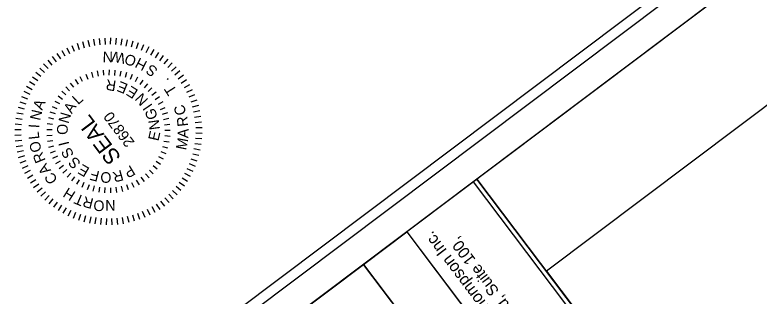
# Model space of a CAD drawing. Extents: x 1262749 to 1264921, y 774795 to 776798.
# Drawn here: x 1263030.3 to 1263352.6, y 776215.8 to 776337.8 of the extents above; entities that cross this region are included whole.
import ezdxf

# ---------------------------------------------------------------- set-up
doc = ezdxf.new("R2010")
doc.units = 0
for name, color, linetype in [('Default', 7, 'Continuous'), ('Prop Vertical Profile Curve Label', 7, 'Continuous'), ('Sheet Border Standard 30in CELL', 7, 'Continuous'), ('Sheet Data Field CELL', 7, 'Continuous'), ('Sheet Layout Plan Border', 7, 'Continuous'), ('Sheet Plan CELL', 7, 'Continuous'), ('Sheet Plan Layout CELL', 7, 'Continuous'), ('Sheet Plot Border Inside CELL', 7, 'Continuous'), ('Sheet Plot Border Outside CELL', 7, 'Continuous')]:
    doc.layers.add(name, color=color, linetype=linetype)

msp = doc.modelspace()

# ---------------------------------------------------------------- linework, layer by layer
at = {"layer": 'Default'}
for p, q in [((1263181.34, 776229.57), (1263200.1, 776243.71)), ((1263200.09, 776243.7), (1263320.41, 776083.96)), ((1263301.64, 776069.83), (1263181.33, 776229.56))]:
    msp.add_line(p, q, dxfattribs=at)
at = {"layer": 'Prop Vertical Profile Curve Label'}
for p, q in [((1263059.59, 776326.23), (1263060.36, 776323.58)), ((1263061.96, 776326.84), (1263062.57, 776324.15)), ((1263064.37, 776327.31), (1263064.81, 776324.58)), ((1263066.8, 776327.63), (1263067.07, 776324.88)), ((1263069.24, 776327.8), (1263069.35, 776325.04)), ((1263071.69, 776327.82), (1263071.63, 776325.06)), ((1263074.14, 776327.7), (1263073.91, 776324.94)), ((1263076.57, 776327.42), (1263076.18, 776324.69)), ((1263078.98, 776327.01), (1263078.43, 776324.3)), ((1263081.37, 776326.44), (1263080.65, 776323.77)), ((1263052.75, 776323.57), (1263053.99, 776321.09)), ((1263054.98, 776324.59), (1263056.06, 776322.05)), ((1263057.26, 776325.49), (1263058.19, 776322.88)), ((1263083.71, 776325.74), (1263082.84, 776323.12)), ((1263086.01, 776324.89), (1263084.98, 776322.33)), ((1263088.26, 776323.91), (1263087.07, 776321.41)), ((1263046.51, 776319.71), (1263048.17, 776317.5)), ((1263048.52, 776321.12), (1263050.04, 776318.81)), ((1263050.6, 776322.4), (1263051.98, 776320.01)), ((1263090.43, 776322.79), (1263089.1, 776320.37)), ((1263092.54, 776321.54), (1263091.06, 776319.2)), ((1263094.57, 776320.17), (1263092.95, 776317.93)), ((1263042.78, 776316.54), (1263044.69, 776314.54)), ((1263044.6, 776318.18), (1263046.39, 776316.07)), ((1263096.52, 776318.68), (1263094.76, 776316.54)), ((1263098.36, 776317.07), (1263096.49, 776315.04)), ((1263041.06, 776314.79), (1263043.09, 776312.91)), ((1263065.94, 776313.55), (1263066.36, 776311.29)), ((1263068.5, 776313.9), (1263068.71, 776311.61)), ((1263071.08, 776314.01), (1263071.06, 776311.7)), ((1263073.66, 776313.86), (1263073.42, 776311.57)), ((1263076.21, 776313.46), (1263075.75, 776311.21)), ((1263100.11, 776315.36), (1263098.12, 776313.45)), ((1263101.75, 776313.54), (1263099.64, 776311.75)), ((1263037.96, 776311), (1263040.21, 776309.38)), ((1263039.46, 776312.94), (1263041.6, 776311.19)), ((1263059.62, 776308.96), (1263058.56, 776311.01)), ((1263060.99, 776312.12), (1263061.84, 776309.98)), ((1263063.43, 776312.95), (1263064.07, 776310.74)), ((1263078.71, 776312.82), (1263078.04, 776310.62)), ((1263081.14, 776311.95), (1263080.25, 776309.82)), ((1263083.47, 776310.84), (1263082.39, 776308.81)), ((1263103.28, 776311.63), (1263101.07, 776309.97)), ((1263035.35, 776306.86), (1263037.77, 776305.52)), ((1263036.59, 776308.97), (1263038.93, 776307.49)), ((1263054.3, 776308.26), (1263055.73, 776306.45)), ((1263056.4, 776309.76), (1263057.65, 776307.82)), ((1263085.69, 776309.51), (1263084.41, 776307.59)), ((1263087.76, 776307.97), (1263086.31, 776306.19)), ((1263104.69, 776309.62), (1263102.39, 776308.1)), ((1263105.98, 776307.54), (1263103.59, 776306.16)), ((1263034.23, 776304.68), (1263036.73, 776303.49)), ((1263050.58, 776304.69), (1263052.32, 776303.19)), ((1263052.35, 776306.56), (1263053.94, 776304.9)), ((1263089.68, 776306.24), (1263088.06, 776304.61)), ((1263091.43, 776304.34), (1263089.65, 776302.87)), ((1263107.14, 776305.38), (1263104.67, 776304.15)), ((1263033.25, 776302.44), (1263035.81, 776301.41)), ((1263047.61, 776300.47), (1263049.61, 776299.33)), ((1263048.99, 776302.65), (1263050.88, 776301.32)), ((1263092.98, 776302.28), (1263091.07, 776300.98)), ((1263108.16, 776303.16), (1263105.62, 776302.07)), ((1263109.06, 776300.88), (1263106.45, 776299.95)), ((1263031.7, 776297.8), (1263034.36, 776297.08)), ((1263032.4, 776300.14), (1263035.02, 776299.26)), ((1263046.45, 776298.16), (1263048.55, 776297.23)), ((1263094.32, 776300.07), (1263092.3, 776298.97)), ((1263093.33, 776296.83), (1263095.45, 776297.73)), ((1263109.81, 776298.55), (1263107.15, 776297.78)), ((1263031.13, 776295.41), (1263033.84, 776294.86)), ((1263045.51, 776295.76), (1263047.7, 776295.03)), ((1263096.34, 776295.33), (1263094.14, 776294.63)), ((1263110.41, 776296.17), (1263107.72, 776295.57)), ((1263030.71, 776293), (1263033.45, 776292.61)), ((1263044.36, 776290.73), (1263046.64, 776290.43)), ((1263044.81, 776293.27), (1263047.05, 776292.75)), ((1263096.99, 776292.83), (1263094.74, 776292.35)), ((1263110.88, 776293.77), (1263108.15, 776293.33)), ((1263111.2, 776291.34), (1263108.45, 776291.07)), ((1263030.32, 776288.11), (1263033.08, 776288.06)), ((1263030.44, 776290.56), (1263033.2, 776290.34)), ((1263044.14, 776288.16), (1263046.45, 776288.08)), ((1263097.41, 776290.28), (1263095.12, 776290.02)), ((1263097.57, 776287.7), (1263095.27, 776287.66)), ((1263111.37, 776288.9), (1263108.61, 776288.79)), ((1263030.34, 776285.67), (1263033.1, 776285.78)), ((1263044.18, 776285.57), (1263046.49, 776285.72)), ((1263097.49, 776285.12), (1263095.19, 776285.31)), ((1263111.39, 776286.45), (1263108.63, 776286.5)), ((1263030.51, 776283.23), (1263033.26, 776283.5)), ((1263030.83, 776280.79), (1263033.56, 776281.24)), ((1263044.48, 776283.01), (1263046.75, 776283.38)), ((1263045.01, 776280.48), (1263047.24, 776281.07)), ((1263097.16, 776282.56), (1263094.89, 776282.97)), ((1263111, 776281.57), (1263108.26, 776281.96)), ((1263111.27, 776284), (1263108.51, 776284.22)), ((1263031.3, 776278.39), (1263033.99, 776279)), ((1263045.79, 776278.02), (1263047.95, 776278.82)), ((1263095.76, 776277.59), (1263093.62, 776278.43)), ((1263096.58, 776280.04), (1263094.36, 776280.67)), ((1263110.58, 776279.16), (1263107.87, 776279.71)), ((1263031.9, 776276.02), (1263034.56, 776276.78)), ((1263032.65, 776273.69), (1263035.26, 776274.62)), ((1263046.8, 776275.64), (1263048.87, 776276.65)), ((1263048.04, 776273.38), (1263050, 776274.57)), ((1263094.71, 776275.24), (1263092.65, 776276.27)), ((1263109.31, 776274.43), (1263106.69, 776275.3)), ((1263110.01, 776276.77), (1263107.35, 776277.49)), ((1263033.55, 776271.4), (1263036.09, 776272.49)), ((1263049.48, 776271.24), (1263051.32, 776272.62)), ((1263091.95, 776270.88), (1263090.14, 776272.29)), ((1263093.44, 776272.99), (1263091.49, 776274.22)), ((1263108.46, 776272.13), (1263105.9, 776273.16)), ((1263034.57, 776269.18), (1263037.04, 776270.42)), ((1263035.73, 776267.03), (1263038.12, 776268.41)), ((1263051.13, 776269.25), (1263052.83, 776270.8)), ((1263052.96, 776267.43), (1263054.51, 776269.14)), ((1263088.41, 776267.13), (1263086.9, 776268.86)), ((1263090.27, 776268.92), (1263088.6, 776270.5)), ((1263106.36, 776267.71), (1263103.94, 776269.04)), ((1263107.48, 776269.88), (1263104.98, 776271.07)), ((1263037.02, 776264.94), (1263039.32, 776266.47)), ((1263054.96, 776265.8), (1263056.33, 776267.65)), ((1263057.11, 776264.36), (1263058.3, 776266.34)), ((1263059.39, 776263.14), (1263060.38, 776265.22)), ((1263081.91, 776262.95), (1263080.96, 776265.05)), ((1263084.21, 776264.13), (1263083.05, 776266.12)), ((1263086.38, 776265.53), (1263085.04, 776267.4)), ((1263103.75, 776263.57), (1263101.5, 776265.19)), ((1263105.12, 776265.59), (1263102.78, 776267.07)), ((1263038.43, 776262.94), (1263040.64, 776264.6)), ((1263039.96, 776261.02), (1263042.07, 776262.81)), ((1263061.77, 776262.15), (1263062.56, 776264.32)), ((1263064.24, 776261.39), (1263064.81, 776263.62)), ((1263066.77, 776260.87), (1263067.12, 776263.15)), ((1263069.34, 776260.6), (1263069.47, 776262.9)), ((1263071.92, 776260.58), (1263071.83, 776262.88)), ((1263074.49, 776260.81), (1263074.18, 776263.09)), ((1263077.03, 776261.28), (1263076.5, 776263.52)), ((1263079.51, 776262), (1263078.76, 776264.18)), ((1263102.25, 776261.62), (1263100.11, 776263.37)), ((1263041.6, 776259.21), (1263043.59, 776261.12)), ((1263043.35, 776257.49), (1263045.22, 776259.52)), ((1263097.11, 776256.39), (1263095.32, 776258.49)), ((1263098.93, 776258.03), (1263097.02, 776260.02)), ((1263100.65, 776259.77), (1263098.62, 776261.65)), ((1263045.19, 776255.89), (1263046.95, 776258.02)), ((1263047.14, 776254.39), (1263048.76, 776256.64)), ((1263049.17, 776253.02), (1263050.65, 776255.36)), ((1263093.19, 776253.45), (1263091.67, 776255.75)), ((1263095.2, 776254.86), (1263093.54, 776257.07)), ((1263051.28, 776251.78), (1263052.61, 776254.19)), ((1263053.46, 776250.66), (1263054.64, 776253.16)), ((1263055.7, 776249.67), (1263056.73, 776252.24)), ((1263086.73, 776249.97), (1263085.65, 776252.51)), ((1263088.96, 776251), (1263087.72, 776253.47)), ((1263091.11, 776252.16), (1263089.73, 776254.55)), ((1263058, 776248.83), (1263058.87, 776251.45)), ((1263060.34, 776248.12), (1263061.06, 776250.79)), ((1263062.73, 776247.56), (1263063.28, 776250.27)), ((1263065.14, 776247.14), (1263065.53, 776249.88)), ((1263067.57, 776246.87), (1263067.8, 776249.62)), ((1263070.02, 776246.74), (1263070.08, 776249.51)), ((1263072.47, 776246.77), (1263072.36, 776249.53)), ((1263074.91, 776246.94), (1263074.64, 776249.69)), ((1263077.34, 776247.26), (1263076.9, 776249.99)), ((1263079.75, 776247.73), (1263079.14, 776250.42)), ((1263082.12, 776248.33), (1263081.35, 776250.99)), ((1263084.45, 776249.08), (1263083.52, 776251.69))]:
    msp.add_line(p, q, dxfattribs=at)
at = {"layer": 'Sheet Border Standard 30in CELL'}
msp.add_lwpolyline([(1263151.63, 776082.06), (1263091.48, 776161.91), (1263181.32, 776229.57), (1263241.46, 776149.72)], close=True, dxfattribs=at)
at = {"layer": 'Sheet Data Field CELL'}
msp.add_lwpolyline([(1263349.24, 776105.68), (1263228.9, 776265.45), (1263200.06, 776243.74), (1263320.41, 776083.96)], close=True, dxfattribs=at)
at = {"layer": 'Sheet Layout Plan Border'}
msp.add_lwpolyline([(1264772.58, 775612.83), (1263930.27, 776731.11), (1263260.5, 776226.63), (1263374.36, 776075.45), (1263205.44, 775948.22), (1263933.87, 774981.11)], close=True, dxfattribs=at)
at = {"layer": 'Sheet Plan CELL'}
msp.add_lwpolyline([(1263061.47, 776139.35), (1263963.95, 774941.17), (1264802.66, 775572.89), (1263900.19, 776771.05)], close=True, dxfattribs=at)
at = {"layer": 'Sheet Plan Layout CELL'}
for points in [[(1263963.99, 774941.16), (1264802.66, 775572.89), (1263900.2, 776771.04), (1263230.42, 776266.56), (1263374.36, 776075.45), (1263205.44, 775948.22)], [(1263374.36, 776075.45), (1263230.41, 776266.58), (1263061.46, 776139.36), (1263205.44, 775948.22)]]:
    msp.add_lwpolyline(points, close=True, dxfattribs=at)
at = {"layer": 'Sheet Plot Border Inside CELL'}
msp.add_lwpolyline([(1264897.01, 775451.8), (1263894.68, 776782.53), (1263051.98, 776147.82), (1264054.31, 774817.07)], close=True, dxfattribs=at)
at = {"layer": 'Sheet Plot Border Outside CELL'}
msp.add_lwpolyline([(1264920.81, 775453.45), (1263907.95, 776798.18), (1263033.3, 776139.38), (1264046.16, 774794.65)], close=True, dxfattribs=at)

# ---------------------------------------------------------------- texts
at = {"layer": 'Prop Vertical Profile Curve Label'}
for s, height, rotation, p in [('N', 4.6, 179.1043, (1263072.81, 776321.85)), ('W', 4.6, 170.2216, (1263078.41, 776321.08)), ('O', 4.6, 161.339, (1263083.33, 776319.58)), ('H', 4.6, 152.5164, (1263087.98, 776317.37)), ('S', 4.6, 143.5138, (1263092.56, 776314.25)), ('.', 4.6, 130.7295, (1263097.31, 776309.58)), ('R', 4.6, 171.4621, (1263074.43, 776309.24)), ('E', 4.6, 157.691, (1263079.62, 776307.66)), ('E', 4.6, 147.7051, (1263084.03, 776305.06)), ('N', 4.6, 132.3131, (1263088.35, 776301.02)), ('T', 4.6, 122.9872, (1263100.68, 776304.87)), ('L', 4.6, 42.7678, (1263057.72, 776298.63)), ('A', 4.6, 67.4143, (1263042.11, 776296.24)), ('A', 4.6, 58.0641, (1263054.97, 776294.71)), ('I', 4.6, 124.6834, (1263090.1, 776298.43)), ('C', 4.6, 105.1918, (1263104.61, 776294.98)), ('N', 4.6, 77.1818, (1263041.22, 776291.77)), ('N', 4.6, 73.3603, (1263053.47, 776290.43)), ('SEAL', 6.909, 126.8972, (1263076.63, 776276.14)), ('26870', 4.602, 126.8972, (1263082.33, 776282.64)), ('G', 4.6, 106.5886, (1263092.22, 776293.16)), ('N', 4.6, 97.8224, (1263093.2, 776288.26)), ('R', 4.6, 96.2194, (1263105.4, 776289.62)), ('I', 4.6, 86.4763, (1263040.87, 776288.62)), ('O', 4.6, 88.6566, (1263053.14, 776285.74)), ('E', 4.6, 76.9673, (1263092.45, 776282.87)), ('A', 4.6, 87.5468, (1263105.36, 776284.31)), ('L', 4.6, 96.0518, (1263040.96, 776284.05)), ('M', 4.6, 78.904, (1263104.48, 776278.95)), ('O', 4.6, 109.188, (1263042.13, 776279.08)), ('I', 4.6, 103.9528, (1263053.93, 776281.69)), ('R', 4.6, 112.2449, (1263043.75, 776274.71)), ('S', 4.6, 119.2491, (1263056.07, 776277.18)), ('S', 4.6, 134.5453, (1263059.14, 776273.74)), ('A', 4.6, 124.2542, (1263046.13, 776270.41)), ('E', 4.6, 149.8416, (1263063, 776271.23)), ('P', 4.6, 211.0266, (1263080.56, 776272.84)), ('C', 4.6, 124.2542, (1263049.08, 776266.33)), ('F', 4.6, 165.1378, (1263067.29, 776269.85)), ('O', 4.6, 180.4341, (1263072.1, 776269.63)), ('R', 4.6, 195.7303, (1263076.5, 776270.66)), ('H', 4.6, 147.9649, (1263056.94, 776260.78)), ('T', 4.6, 157.3968, (1263060.77, 776259.02)), ('R', 4.6, 165.5578, (1263064.69, 776258.09)), ('O', 4.6, 178.6145, (1263069.17, 776257.29)), ('N', 4.6, 180.5739, (1263073.87, 776257.51))]:
    msp.add_text(s, height=height, rotation=rotation, dxfattribs=at).set_placement(p)
at = {"layer": 'Sheet Data Field CELL'}
for s, height, p in [('Johnson, Mirmiran, & Thompson Inc.', 5.1112, (1263278.23, 776155.32)), ('4700 Falls of Neuse Rd, Suite 100, ', 4.9652, (1263284.22, 776159.83))]:
    msp.add_text(s, height=height, rotation=126.9874, dxfattribs=at).set_placement(p)

doc.saveas('drawing.dxf')
